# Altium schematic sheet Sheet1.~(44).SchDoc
size A
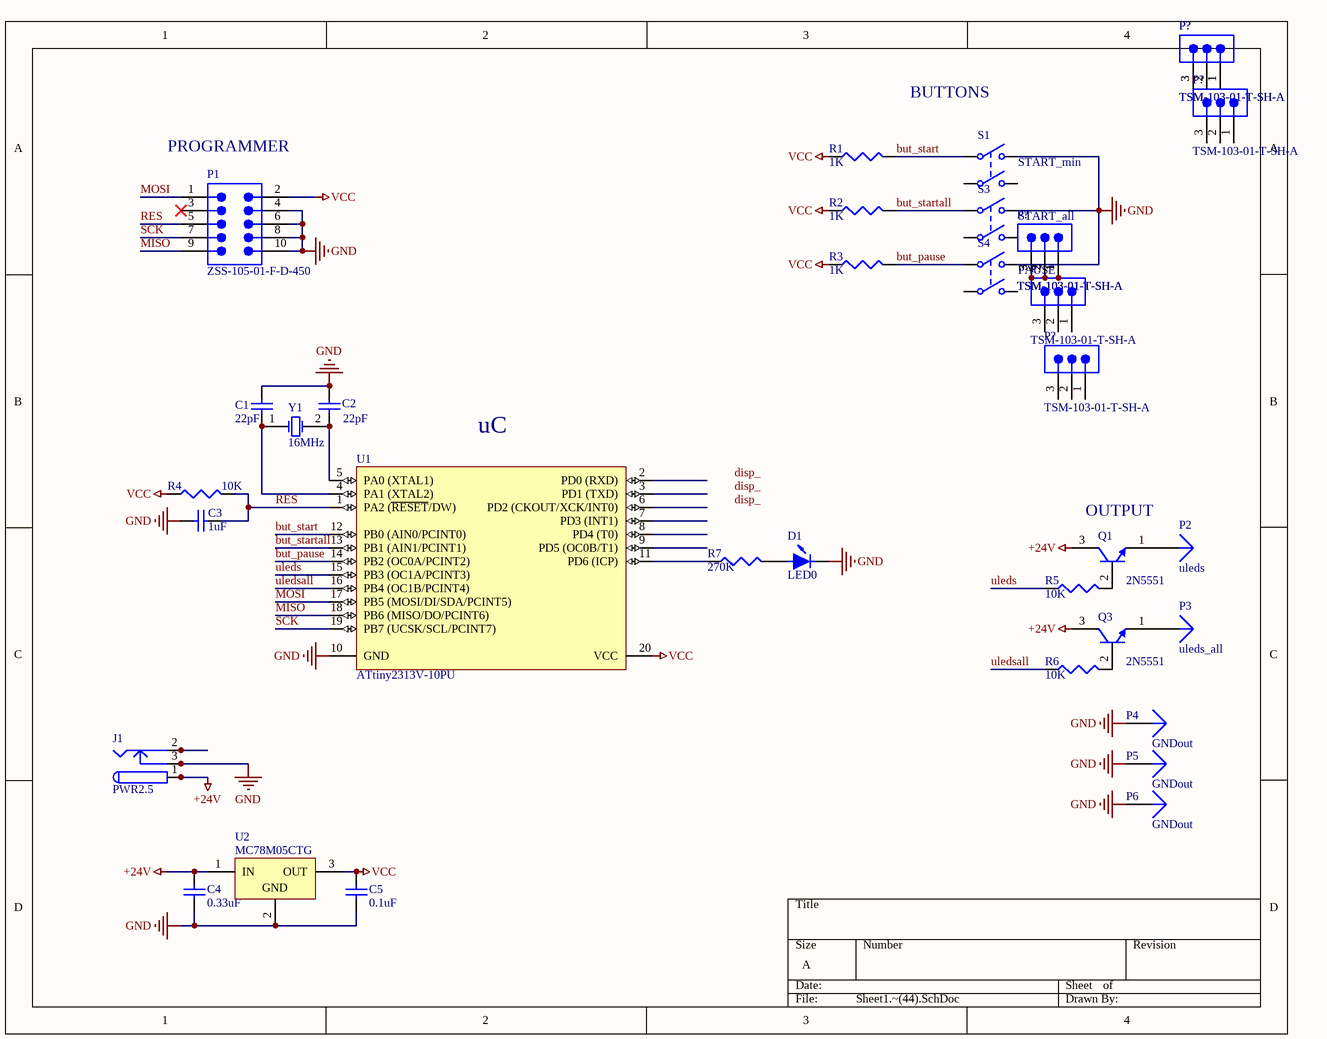
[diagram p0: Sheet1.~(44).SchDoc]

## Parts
(Parts that share a designator on the sheet are numbered #1, #2 ... from top to bottom, then left to right.)
C1  value 22pF  [CAPC1608L]  (hidden comment: Cap Semi)
C2  value 22pF  [CAPC1608L]  (hidden comment: Cap Semi)
C3  value 1uF  [CAPC1608L]  (hidden comment: Cap Semi)
C4  value 0.33uF  [CAPC1608L]  (hidden comment: Cap Semi)
C5  value 0.1uF  [CAPC1608L]  (hidden comment: Cap Semi)
D1  LED0  [LED-0]
J1  PWR2.5  [KLD-0202]
P1  ZSS-105-01-F-D-450  [SMTC-ZSS-105-01-X-D-450]
P2  uleds  [PIN1]
P3  uleds_all  [PIN1]
P4  GNDout  [PIN1]
P5  GNDout  [PIN1]
P6  GNDout  [PIN1]
P?#1  TSM-103-01-T-SH-A  [SMTC-TSM-103-01-X-SH-A]
P?#2  TSM-103-01-T-SH-A  [SMTC-TSM-103-01-X-SH-A]
P?#3  TSM-103-01-T-SH-A  [SMTC-TSM-103-01-X-SH-A]
P?#4  TSM-103-01-T-SH-A  [SMTC-TSM-103-01-X-SH-A]
P?#5  TSM-103-01-T-SH-A  [SMTC-TSM-103-01-X-SH-A]
P?#6  TSM-103-01-T-SH-A  [SMTC-TSM-103-01-X-SH-A]
P?#7  TSM-103-01-T-SH-A  [SMTC-TSM-103-01-X-SH-A]
P?#8  TSM-103-01-T-SH-A  [SMTC-TSM-103-01-X-SH-A]
Q1  2N5551  [ONSC-TO-92-3-29-11_AM_BL]
Q3  2N5551  [ONSC-TO-92-3-29-11_AM_BL]
R1  value 1K  [CAPC1608L]  (hidden comment: Res3)
R2  value 1K  [CAPC1608L]  (hidden comment: Res3)
R3  value 1K  [CAPC1608L]  (hidden comment: Res3)
R4  value 10K  [CAPC1608L]  (hidden comment: Res3)
R5  value 10K  [CAPC1608L]  (hidden comment: Res3)
R6  value 10K  [CAPC1608L]  (hidden comment: Res3)
R7  value 270K  [CAPC1608L]  (hidden comment: Res3)
S1  START_min  [key]
S3  START_all  [key]
S4  PAUSE  [key]
U1  ATtiny2313V-10PU  [20P3]
U2  MC78M05CTG  [TO220]
Y1  16MHz  [HC-49U]

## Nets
+24V: C4.2 J1.1 J1.1A J1.1B Q1.3(C) Q3.3(C) U2.1(IN)
GND: C1.1 C2.1 C3.2 C4.1 C5.1 D1.2(K) J1.3 J1.3A J1.3B P1.4 P1.6 P1.8 P1.10 P4.1 P5.1 P6.1 S1.2(NO1) S3.2(NO1) S4.2(NO1) U1.10(GND) U2.2(GND)
VCC: C5.2 P1.2 R1.1 R2.1 R3.1 R4.1 U1.20(VCC) U2.3(OUT)
but_pause: R3.2 S4.1(COMMON1) U1.14(PB2_(OC0A/PCINT2))
but_start: R1.2 S1.1(COMMON1) U1.12(PB0_(AIN0/PCINT0))
but_startall: R2.2 S3.1(COMMON1) U1.13(PB1_(AIN1/PCINT1))
MISO: P1.9 U1.18(PB6_(MISO/DO/PCINT6))
MOSI: P1.1 U1.17(PB5_(MOSI/DI/SDA/PCINT5))
RES: C3.1 P1.5 R4.2 U1.1(PA2_(~{RESET}/DW))
SCK: P1.7 U1.19(PB7_(UCSK/SCL/PCINT7))
uleds: R5.1 U1.15(PB3_(OC1A/PCINT3))
uledsall: R6.1 U1.16(PB4_(OC1B/PCINT4))
NetC1_2: C1.2 U1.4(PA1_(XTAL2)) Y1.1(OSC1)
NetC2_2: C2.2 U1.5(PA0_(XTAL1)) Y1.2(OSC2)
NetD1_1: D1.1(A) R7.2
NetJ1_2: J1.2 J1.2A J1.2B
NetP2_1: P2.1 Q1.1(E)
NetP3_1: P3.1 Q3.1(E)
NetP?#1_1: P?#1.1 P?#2.1
NetP?#1_2: P?#1.2 P?#2.2
NetP?#1_3: P?#1.3 P?#2.3
NetP?#4_1: P?#4.1 P?#5.1 P?#6.1
NetP?#4_2: P?#4.2 P?#5.2 P?#6.2
NetP?#4_3: P?#4.3 P?#5.3 P?#6.3
NetQ1_2: Q1.2(B) R5.2
NetQ3_2: Q3.2(B) R6.2
NetR7_1: R7.1 U1.11(PD6_(ICP))

Not connected (* = marked no-connect by the designer): P1 3*; P?#3 1 2 3; P?#7 1 2 3; P?#8 1 2 3; S1 3(COMMON2) 4(NO2); S3 3(COMMON2) 4(NO2); S4 3(COMMON2) 4(NO2); U1 2(PD0_(RXD)) 3(PD1_(TXD)) 6(PD2_(CKOUT/XCK/INT0)) 7(PD3_(INT1)) 8(PD4_(T0)) 9(PD5_(OC0B/T1))

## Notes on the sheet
- BUTTONS
- (near P1) PROGRAMMER
- (near U1) uC
- (near Q1) OUTPUT
- Labels drawn without touching a wire or pin: disp_

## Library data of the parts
C1-C5 = Cap Semi: Capacitor (Semiconductor SIM Model)
D1 = LED0: Typical INFRARED GaAs LED
J1 = PWR2.5: Low Voltage Power Supply Connector
P1 = CMP-1024-00461-1: Manufacturer: Samtec; Pitch: 2.54 mm
P2-P6 = Plug
P?#1-P?#8 = CMP-1024-00211-1: Manufacturer: Samtec; Pitch: 2.54 mm
Q1 Q3 = CMP-1048-01479-1: Amplifier Transistor, NPN Silicon, 3-Pin TO-92, Pb-Free, Tape and Reel; PartNumber: 2N5551RL1G; Manufacturer: On Semiconductor; fT Min (MHz): 100; IC Continuous (A): 0.6
R1-R7 = Res3: Resistor
S1 S3 S4 = SW-DPST: Double-Pole, Single-Throw Switch
U1 = CMP-0093-00017-1: Low Power tinyAVR® 8-Bit Microcontroller, 2K Flash Memory, 10MHz, Industrial Temperature, 20-Lead PDIP, Pb-Free
U2 = CMP-0244-00483-1: Positive Voltage Regulator, 5V, 3-Pin TO-220
Y1 = XTAL: Crystal Oscillator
